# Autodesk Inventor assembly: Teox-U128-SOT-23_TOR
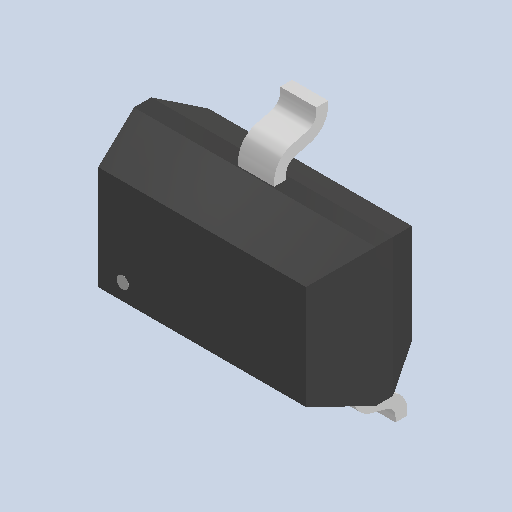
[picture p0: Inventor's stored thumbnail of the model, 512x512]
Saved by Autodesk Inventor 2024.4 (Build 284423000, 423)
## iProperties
Created: 2025-05
Part Number: Teox-U128-SOT-23_TOR
Document SubType Name: Assembly
Designer: AdminForWorker
Title: Teox-U128-SOT-23_TOR
Author: AdminForWorker
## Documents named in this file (2)
- c:\worker\convert-fusion-r02-cosv3\tmp\job-1\2\temp\files\be827049-a7f2-47ea-a815-8d9efd6bfce9\Teox-U128-SOT-23_TOR.iam
- c:\worker\convert-fusion-r02-cosv3\tmp\job-1\2\temp\files\be827049-a7f2-47ea-a815-8d9efd6bfce9\COMPOUND.ipt
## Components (1 placed, 1 different names)
1. COMPOUND:1
